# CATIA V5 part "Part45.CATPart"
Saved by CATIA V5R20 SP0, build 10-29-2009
Part number: IA 2275SF
Revision: ANY
Definition: UNKNOWN
Nomenclature: IA 2275SF
Source: Unknown
Bounding box of the stored display mesh (mm): x -1.102 to 1.102, y -0.001 to 7.75, z -1.102 to 1.102
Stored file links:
  C:\Users\Utente\Desktop\IO LAVORO\3D X SITO CF\CUMSA\3D files FA\FA 042200\Part45.CATPart

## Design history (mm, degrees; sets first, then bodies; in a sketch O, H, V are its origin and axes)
Body1 "Cortar-Extruir2" (main body)
  Solid1: solid without history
